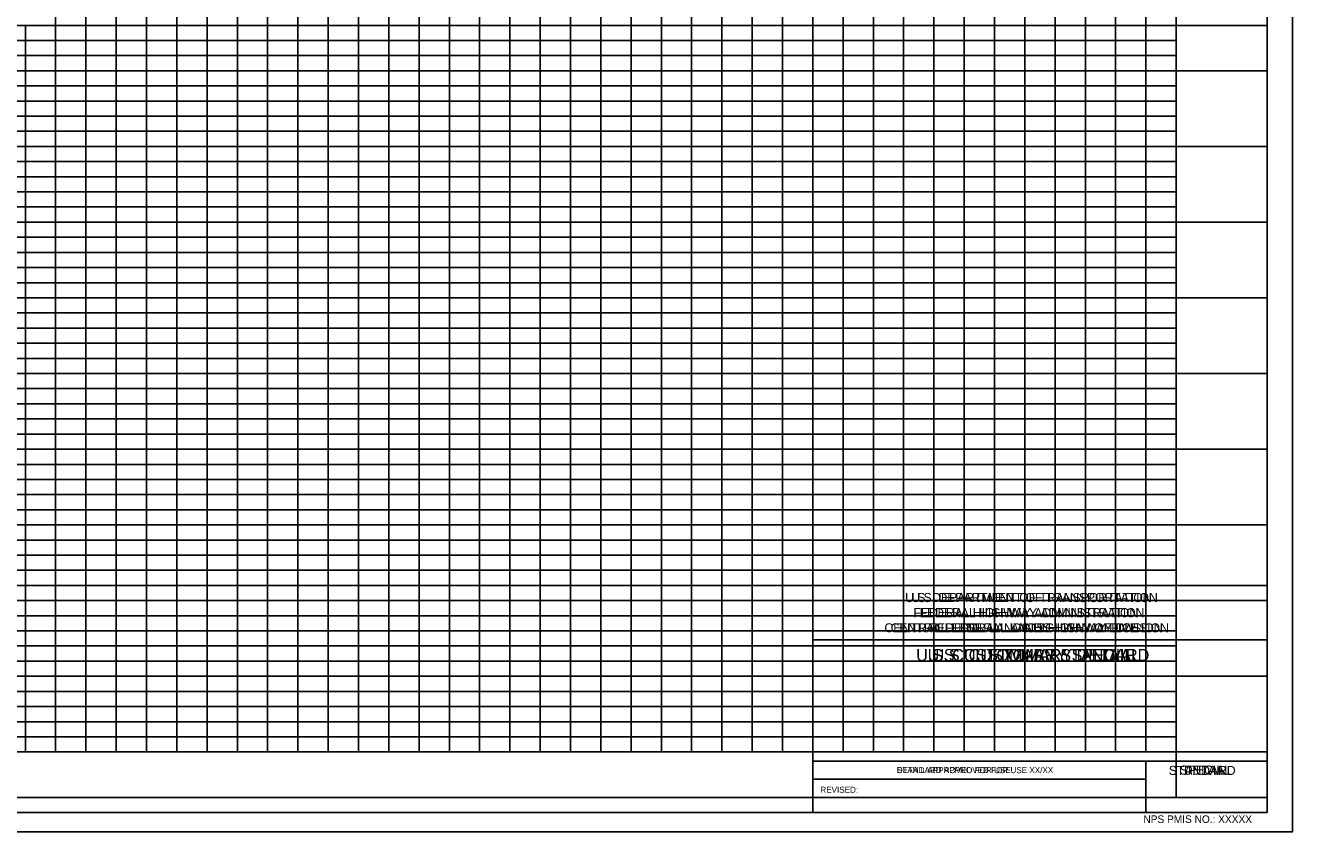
# Model space of a CAD drawing. Extents: x -87 to 2484, y -13 to 1056.
# Drawn here: x 740 to 1577, y -13 to 520 of the extents above; entities that cross this region are included whole.
import ezdxf

# ---------------------------------------------------------------- set-up
doc = ezdxf.new("R2010")
doc.units = 0
for name, color, linetype in [('D_CFL_Clip_Boundary_1', 7, 'Continuous'), ('D_CFL_Clip_Boundary_2', 7, 'Continuous'), ('D_CFL_Sheet_Border_ PlotShape', 7, 'Continuous'), ('D_CFL_Sheet_Border_Base', 7, 'Continuous'), ('D_CFL_Sheet_Border_Box', 7, 'Continuous'), ('D_CFL_Sheet_Border_Detail', 7, 'Continuous'), ('D_CFL_Sheet_Border_General', 7, 'Continuous'), ('D_CFL_Sheet_Border_NPS_Pkg', 7, 'Continuous'), ('D_CFL_Sheet_Border_Plan_Plan', 7, 'Continuous'), ('D_CFL_Sheet_Border_PnP', 7, 'Continuous'), ('D_CFL_Sheet_Border_Profile', 7, 'Continuous'), ('D_CFL_Sheet_Border_Special', 7, 'Continuous'), ('D_CFL_Sheet_Border_Standard', 7, 'Continuous')]:
    doc.layers.add(name, color=color, linetype=linetype)

msp = doc.modelspace()

# ---------------------------------------------------------------- linework, layer by layer
at = {"layer": 'D_CFL_Clip_Boundary_1'}
msp.add_lwpolyline([(0, 520), (0, 1040), (1305, 1040), (1305, 1000), (1560, 1000), (1560, 520)], close=True, dxfattribs=at)
msp.add_lwpolyline([(0, 520), (0, 1040), (1305, 1040), (1305, 1000), (1560, 1000), (1560, 520)], close=True, dxfattribs=at)
at = {"layer": 'D_CFL_Clip_Boundary_2'}
msp.add_lwpolyline([(1500, 520), (60, 520), (60, 40), (1500, 40)], close=True, dxfattribs=at)
msp.add_lwpolyline([(1500, 520), (60, 520), (60, 40), (1500, 40)], close=True, dxfattribs=at)
at = {"layer": 'D_CFL_Sheet_Border_ PlotShape'}
msp.add_lwpolyline([(-86.9, -12.66), (1576.9, -12.66), (1576.9, 1052.65), (-86.9, 1052.65)], close=True, dxfattribs=at)
msp.add_lwpolyline([(-86.9, -12.66), (1576.9, -12.66), (1576.9, 1052.65), (-86.9, 1052.65)], close=True, dxfattribs=at)
at = {"layer": 'D_CFL_Sheet_Border_Base'}
msp.add_lwpolyline([(0, 0), (1560, 0), (1560, 1040), (0, 1040)], close=True, dxfattribs=at)
msp.add_lwpolyline([(0, 0), (1560, 0), (1560, 1040), (0, 1040)], close=True, dxfattribs=at)
at = {"layer": 'D_CFL_Sheet_Border_Box'}
for p, q in [((1260, 0), (1260, 114)), ((1260, 114), (1560.01, 114)), ((1260, 0), (1260, 114)), ((1260, 114), (1560.01, 114)), ((1410.01, 57), (1410.01, 57)), ((1410.01, 57), (1410.01, 57))]:
    msp.add_line(p, q, dxfattribs=at)
at = {"layer": 'D_CFL_Sheet_Border_Detail'}
for p, q in [((1260, 114), (1560.01, 114)), ((1260, 114), (1560.01, 114)), ((1410.01, 69), (1410.01, 69)), ((1410.01, 69), (1410.01, 69)), ((1260, 34), (1560.01, 34)), ((1260, 34), (1560.01, 34)), ((1480.01, 34), (1480.01, 0)), ((1480.01, 34), (1480.01, 0)), ((1260, 22), (1480.01, 22)), ((1260, 22), (1480.01, 22))]:
    msp.add_line(p, q, dxfattribs=at)
msp.add_lwpolyline([(1560.01, 150), (1260, 150), (1260, 0)], dxfattribs=at)
msp.add_lwpolyline([(1560.01, 150), (1260, 150), (1260, 0)], dxfattribs=at)
at = {"layer": 'D_CFL_Sheet_Border_General'}
for p, q in [((1260, 114), (1560.01, 114)), ((1260, 114), (1560.01, 114)), ((1410.01, 57), (1410.01, 57)), ((1410.01, 57), (1410.01, 57))]:
    msp.add_line(p, q, dxfattribs=at)
msp.add_lwpolyline([(1560.01, 150), (1260, 150), (1260, 0)], dxfattribs=at)
msp.add_lwpolyline([(1560.01, 150), (1260, 150), (1260, 0)], dxfattribs=at)
at = {"layer": 'D_CFL_Sheet_Border_Plan_Plan'}
for p, q in [((1260, 0), (1260, 114)), ((1260, 114), (1560.01, 114)), ((1260, 0), (1260, 114)), ((1260, 114), (1560.01, 114)), ((1410.01, 57), (1410.01, 57)), ((1410.01, 57), (1410.01, 57))]:
    msp.add_line(p, q, dxfattribs=at)
at = {"layer": 'D_CFL_Sheet_Border_PnP'}
for p, q in [((0, 520), (1560, 520)), ((0, 520), (1560, 520)), ((740, 39.72), (740, 519.72)), ((740, 39.72), (740, 519.72)), ((760, 39.72), (760, 519.72)), ((760, 39.72), (760, 519.72)), ((780, 40), (780, 520)), ((780, 40), (780, 520)), ((800, 39.72), (800, 519.72)), ((800, 39.72), (800, 519.72)), ((820, 39.72), (820, 519.72)), ((820, 39.72), (820, 519.72)), ((840, 39.72), (840, 519.72)), ((840, 39.72), (840, 519.72)), ((860, 39.72), (860, 519.72)), ((860, 39.72), (860, 519.72)), ((880, 40), (880, 520)), ((880, 40), (880, 520)), ((900, 39.72), (900, 519.72)), ((900, 39.72), (900, 519.72)), ((920, 39.72), (920, 519.72)), ((920, 39.72), (920, 519.72)), ((940, 39.72), (940, 519.72)), ((940, 39.72), (940, 519.72)), ((960, 39.72), (960, 519.72)), ((960, 39.72), (960, 519.72)), ((980, 40), (980, 520)), ((980, 40), (980, 520)), ((1000, 39.72), (1000, 519.72)), ((1000, 39.72), (1000, 519.72)), ((1020, 39.72), (1020, 519.72)), ((1020, 39.72), (1020, 519.72)), ((1040, 39.72), (1040, 519.72)), ((1040, 39.72), (1040, 519.72)), ((1060, 39.72), (1060, 519.72)), ((1060, 39.72), (1060, 519.72)), ((1080, 40), (1080, 520)), ((1080, 40), (1080, 520)), ((1100, 39.72), (1100, 519.72)), ((1100, 39.72), (1100, 519.72)), ((1120, 39.72), (1120, 519.72)), ((1120, 39.72), (1120, 519.72)), ((1140, 39.72), (1140, 519.72)), ((1140, 39.72), (1140, 519.72)), ((1160, 39.72), (1160, 519.72)), ((1160, 39.72), (1160, 519.72)), ((1180, 40), (1180, 520)), ((1180, 40), (1180, 520)), ((1200, 39.72), (1200, 519.72)), ((1200, 39.72), (1200, 519.72)), ((1220, 39.72), (1220, 519.72)), ((1220, 39.72), (1220, 519.72)), ((1240, 39.72), (1240, 519.72)), ((1240, 39.72), (1240, 519.72)), ((1260, 39.72), (1260, 519.72)), ((1260, 39.72), (1260, 519.72)), ((1280, 40), (1280, 520)), ((1280, 40), (1280, 520)), ((1300, 39.72), (1300, 519.72)), ((1300, 39.72), (1300, 519.72)), ((1320, 39.72), (1320, 519.72)), ((1320, 39.72), (1320, 519.72)), ((1340, 39.72), (1340, 519.72)), ((1340, 39.72), (1340, 519.72)), ((1360, 39.72), (1360, 519.72)), ((1360, 39.72), (1360, 519.72)), ((1380, 40), (1380, 520)), ((1380, 40), (1380, 520)), ((1400, 39.72), (1400, 519.72)), ((1400, 39.72), (1400, 519.72)), ((1420, 39.72), (1420, 519.72)), ((1420, 39.72), (1420, 519.72)), ((1440, 39.72), (1440, 519.72)), ((1440, 39.72), (1440, 519.72)), ((1460, 39.72), (1460, 519.72)), ((1460, 39.72), (1460, 519.72)), ((1480, 40), (1480, 520)), ((1480, 40), (1480, 520)), ((1500, 520), (1500, 10)), ((1500, 520), (1500, 10)), ((60, 510), (1500, 510)), ((60, 510), (1500, 510)), ((60, 500), (1500, 500)), ((60, 500), (1500, 500)), ((60, 490), (1500, 490)), ((60, 490), (1500, 490)), ((1560, 490), (1500, 490)), ((1560, 490), (1500, 490)), ((60, 480), (1500, 480)), ((60, 480), (1500, 480)), ((60, 470), (1500, 470)), ((60, 470), (1500, 470)), ((60, 460), (1500, 460)), ((60, 460), (1500, 460)), ((60, 450), (1500, 450)), ((60, 450), (1500, 450)), ((60, 440), (1500, 440)), ((60, 440), (1500, 440)), ((1560, 440), (1500, 440)), ((1560, 440), (1500, 440)), ((60, 430), (1500, 430)), ((60, 430), (1500, 430)), ((60, 420), (1500, 420)), ((60, 420), (1500, 420)), ((60, 410), (1500, 410)), ((60, 410), (1500, 410)), ((60, 400), (1500, 400)), ((60, 400), (1500, 400)), ((60, 390), (1500, 390)), ((60, 390), (1500, 390)), ((1560, 390), (1500, 390)), ((1560, 390), (1500, 390)), ((60, 380), (1500, 380)), ((60, 380), (1500, 380)), ((60, 370), (1500, 370)), ((60, 370), (1500, 370)), ((60, 360), (1500, 360)), ((60, 360), (1500, 360)), ((60, 350), (1500, 350)), ((60, 350), (1500, 350)), ((60, 340), (1500, 340)), ((60, 340), (1500, 340)), ((1560, 340), (1500, 340)), ((1560, 340), (1500, 340)), ((60, 330), (1500, 330)), ((60, 330), (1500, 330)), ((60, 320), (1500, 320)), ((60, 320), (1500, 320)), ((60, 310), (1500, 310)), ((60, 310), (1500, 310)), ((60, 300), (1500, 300)), ((60, 300), (1500, 300)), ((60, 290), (1500, 290)), ((60, 290), (1500, 290)), ((1560, 290), (1500, 290)), ((1560, 290), (1500, 290)), ((60, 280), (1500, 280)), ((60, 280), (1500, 280)), ((60, 270), (1500, 270)), ((60, 270), (1500, 270)), ((60, 260), (1500, 260)), ((60, 260), (1500, 260)), ((60, 250), (1500, 250)), ((60, 250), (1500, 250)), ((60, 240), (1500, 240)), ((60, 240), (1500, 240)), ((1560, 240), (1500, 240)), ((1560, 240), (1500, 240)), ((60, 230), (1500, 230)), ((60, 230), (1500, 230)), ((60, 220), (1500, 220)), ((60, 220), (1500, 220)), ((60, 210), (1500, 210)), ((60, 210), (1500, 210)), ((60, 200), (1500, 200)), ((60, 200), (1500, 200)), ((60, 190), (1500, 190)), ((60, 190), (1500, 190)), ((1560, 190), (1500, 190)), ((1560, 190), (1500, 190)), ((60, 180), (1500, 180)), ((60, 180), (1500, 180)), ((60, 170), (1500, 170)), ((60, 170), (1500, 170)), ((60, 160), (1500, 160)), ((60, 160), (1500, 160)), ((60, 150), (1500, 150)), ((60, 150), (1500, 150)), ((60, 140), (1500, 140)), ((60, 140), (1500, 140)), ((1560, 140), (1500, 140)), ((1560, 140), (1500, 140)), ((60, 130), (1500, 130)), ((60, 130), (1500, 130)), ((60, 120), (1500, 120)), ((60, 120), (1500, 120)), ((60, 110), (1500, 110)), ((60, 110), (1500, 110)), ((60, 100), (1500, 100)), ((60, 100), (1500, 100)), ((60, 90), (1500, 90)), ((60, 90), (1500, 90)), ((1560, 90), (1500, 90)), ((1560, 90), (1500, 90)), ((60, 80), (1500, 80)), ((60, 80), (1500, 80)), ((60, 70), (1500, 70)), ((60, 70), (1500, 70)), ((60, 60), (1500, 60)), ((60, 60), (1500, 60)), ((60, 50), (1500, 50)), ((60, 50), (1500, 50)), ((60, 40), (1500, 40)), ((60, 40), (1500, 40)), ((1560, 40), (1500, 40)), ((1560, 40), (1500, 40)), ((0, 10), (1560, 10)), ((0, 10), (1560, 10))]:
    msp.add_line(p, q, dxfattribs=at)
at = {"layer": 'D_CFL_Sheet_Border_Profile'}
for p, q in [((760, 40), (760, 990)), ((760, 40), (760, 990)), ((780, 40), (780, 990)), ((780, 40), (780, 990)), ((800, 40), (800, 990)), ((800, 40), (800, 990)), ((820, 40), (820, 990)), ((820, 40), (820, 990)), ((840, 40), (840, 990)), ((840, 40), (840, 990)), ((860, 40), (860, 990)), ((860, 40), (860, 990)), ((880, 40), (880, 990)), ((880, 40), (880, 990)), ((900, 40), (900, 990)), ((900, 40), (900, 990)), ((920, 40), (920, 990)), ((920, 40), (920, 990)), ((940, 40), (940, 990)), ((940, 40), (940, 990)), ((960, 40), (960, 990)), ((960, 40), (960, 990)), ((980, 40), (980, 990)), ((980, 40), (980, 990)), ((1000, 40), (1000, 990)), ((1000, 40), (1000, 990)), ((1020, 40), (1020, 990)), ((1020, 40), (1020, 990)), ((1040, 40), (1040, 990)), ((1040, 40), (1040, 990)), ((1060, 40), (1060, 990)), ((1060, 40), (1060, 990)), ((1080, 40), (1080, 990)), ((1080, 40), (1080, 990)), ((1100, 40), (1100, 990)), ((1100, 40), (1100, 990)), ((1120, 40), (1120, 990)), ((1120, 40), (1120, 990)), ((1140, 40), (1140, 990)), ((1140, 40), (1140, 990)), ((1160, 40), (1160, 990)), ((1160, 40), (1160, 990)), ((1180, 40), (1180, 990)), ((1180, 40), (1180, 990)), ((1200, 40), (1200, 990)), ((1200, 40), (1200, 990)), ((1220, 40), (1220, 990)), ((1220, 40), (1220, 990)), ((1240, 40), (1240, 990)), ((1240, 40), (1240, 990)), ((1260, 40), (1260, 990)), ((1260, 40), (1260, 990)), ((1280, 40), (1280, 990)), ((1280, 40), (1280, 990)), ((1300, 40), (1300, 990)), ((1300, 40), (1300, 990)), ((1320, 40), (1320, 990)), ((1320, 40), (1320, 990)), ((1340, 40), (1340, 990)), ((1340, 40), (1340, 990)), ((1360, 40), (1360, 990)), ((1360, 40), (1360, 990)), ((1380, 40), (1380, 990)), ((1380, 40), (1380, 990)), ((1400, 40), (1400, 990)), ((1400, 40), (1400, 990)), ((1420, 40), (1420, 990)), ((1420, 40), (1420, 990)), ((1440, 40), (1440, 990)), ((1440, 40), (1440, 990)), ((1460, 40), (1460, 990)), ((1460, 40), (1460, 990)), ((1480, 40), (1480, 990)), ((1480, 40), (1480, 990)), ((1500, 990), (1500, 10)), ((1500, 990), (1500, 10)), ((60, 520), (1500, 520)), ((60, 520), (1500, 520)), ((60, 510), (1500, 510)), ((60, 510), (1500, 510)), ((60, 500), (1500, 500)), ((60, 500), (1500, 500)), ((60, 490), (1500, 490)), ((60, 490), (1500, 490)), ((1560, 490), (1500, 490)), ((1560, 490), (1500, 490)), ((60, 480), (1500, 480)), ((60, 480), (1500, 480)), ((60, 470), (1500, 470)), ((60, 470), (1500, 470)), ((60, 460), (1500, 460)), ((60, 460), (1500, 460)), ((60, 450), (1500, 450)), ((60, 450), (1500, 450)), ((60, 440), (1500, 440)), ((60, 440), (1500, 440)), ((1560, 440), (1500, 440)), ((1560, 440), (1500, 440)), ((60, 430), (1500, 430)), ((60, 430), (1500, 430)), ((60, 420), (1500, 420)), ((60, 420), (1500, 420)), ((60, 410), (1500, 410)), ((60, 410), (1500, 410)), ((60, 400), (1500, 400)), ((60, 400), (1500, 400)), ((60, 390), (1500, 390)), ((60, 390), (1500, 390)), ((1560, 390), (1500, 390)), ((1560, 390), (1500, 390)), ((60, 380), (1500, 380)), ((60, 380), (1500, 380)), ((60, 370), (1500, 370)), ((60, 370), (1500, 370)), ((60, 360), (1500, 360)), ((60, 360), (1500, 360)), ((60, 350), (1500, 350)), ((60, 350), (1500, 350)), ((60, 340), (1500, 340)), ((60, 340), (1500, 340)), ((1560, 340), (1500, 340)), ((1560, 340), (1500, 340)), ((60, 330), (1500, 330)), ((60, 330), (1500, 330)), ((60, 320), (1500, 320)), ((60, 320), (1500, 320)), ((60, 310), (1500, 310)), ((60, 310), (1500, 310)), ((60, 300), (1500, 300)), ((60, 300), (1500, 300)), ((60, 290), (1500, 290)), ((60, 290), (1500, 290)), ((1560, 290), (1500, 290)), ((1560, 290), (1500, 290)), ((60, 280), (1500, 280)), ((60, 280), (1500, 280)), ((60, 270), (1500, 270)), ((60, 270), (1500, 270)), ((60, 260), (1500, 260)), ((60, 260), (1500, 260)), ((60, 250), (1500, 250)), ((60, 250), (1500, 250)), ((60, 240), (1500, 240)), ((60, 240), (1500, 240)), ((1560, 240), (1500, 240)), ((1560, 240), (1500, 240)), ((60, 230), (1500, 230)), ((60, 230), (1500, 230)), ((60, 220), (1500, 220)), ((60, 220), (1500, 220)), ((60, 210), (1500, 210)), ((60, 210), (1500, 210)), ((60, 200), (1500, 200)), ((60, 200), (1500, 200)), ((60, 190), (1500, 190)), ((60, 190), (1500, 190)), ((1560, 190), (1500, 190)), ((1560, 190), (1500, 190)), ((60, 180), (1500, 180)), ((60, 180), (1500, 180)), ((60, 170), (1500, 170)), ((60, 170), (1500, 170)), ((60, 160), (1500, 160)), ((60, 160), (1500, 160)), ((60, 150), (1500, 150)), ((60, 150), (1500, 150)), ((60, 140), (1500, 140)), ((60, 140), (1500, 140)), ((1560, 140), (1500, 140)), ((1560, 140), (1500, 140)), ((60, 130), (1500, 130)), ((60, 130), (1500, 130)), ((60, 120), (1500, 120)), ((60, 120), (1500, 120)), ((60, 110), (1500, 110)), ((60, 110), (1500, 110)), ((60, 100), (1500, 100)), ((60, 100), (1500, 100)), ((60, 90), (1500, 90)), ((60, 90), (1500, 90)), ((1560, 90), (1500, 90)), ((1560, 90), (1500, 90)), ((60, 80), (1500, 80)), ((60, 80), (1500, 80)), ((60, 70), (1500, 70)), ((60, 70), (1500, 70)), ((60, 60), (1500, 60)), ((60, 60), (1500, 60)), ((60, 50), (1500, 50)), ((60, 50), (1500, 50)), ((60, 40), (1500, 40)), ((60, 40), (1500, 40)), ((1560, 40), (1500, 40)), ((1560, 40), (1500, 40)), ((0, 10), (1560, 10)), ((0, 10), (1560, 10))]:
    msp.add_line(p, q, dxfattribs=at)
at = {"layer": 'D_CFL_Sheet_Border_Special'}
for p, q in [((1260, 114), (1560.01, 114)), ((1260, 114), (1560.01, 114)), ((1410.01, 69), (1410.01, 69)), ((1410.01, 69), (1410.01, 69)), ((1260, 34), (1560.01, 34)), ((1260, 34), (1560.01, 34)), ((1480.01, 34), (1480.01, 0)), ((1480.01, 34), (1480.01, 0)), ((1260, 22), (1480.01, 22)), ((1260, 22), (1480.01, 22))]:
    msp.add_line(p, q, dxfattribs=at)
msp.add_lwpolyline([(1560.01, 150), (1260, 150), (1260, 0)], dxfattribs=at)
msp.add_lwpolyline([(1560.01, 150), (1260, 150), (1260, 0)], dxfattribs=at)
at = {"layer": 'D_CFL_Sheet_Border_Standard'}
for p, q in [((1260, 114), (1560.01, 114)), ((1260, 114), (1560.01, 114)), ((1410.01, 69), (1410.01, 69)), ((1410.01, 69), (1410.01, 69)), ((1260, 34), (1560.01, 34)), ((1260, 34), (1560.01, 34)), ((1480.01, 34), (1480.01, 0)), ((1480.01, 34), (1480.01, 0)), ((1260, 22), (1480.01, 22)), ((1260, 22), (1480.01, 22))]:
    msp.add_line(p, q, dxfattribs=at)
msp.add_lwpolyline([(1560.01, 150), (1260, 150), (1260, 0)], dxfattribs=at)
msp.add_lwpolyline([(1560.01, 150), (1260, 150), (1260, 0)], dxfattribs=at)

# ---------------------------------------------------------------- texts
at = {"layer": 'D_CFL_Sheet_Border_Detail'}
for s, height, p in [('U.S. DEPARTMENT OF TRANSPORTATION', 6, (1321.03, 139)), ('U.S. DEPARTMENT OF TRANSPORTATION', 6, (1321.03, 139)), ('FEDERAL HIGHWAY ADMINISTRATION', 6, (1326.45, 129)), ('FEDERAL HIGHWAY ADMINISTRATION', 6, (1326.45, 129)), ('CENTRAL FEDERAL LANDS HIGHWAY DIVISION', 6, (1307.33, 119)), ('CENTRAL FEDERAL LANDS HIGHWAY DIVISION', 6, (1307.33, 119)), ('U.S. CUSTOMARY DETAIL', 8, (1339.14, 100)), ('U.S. CUSTOMARY DETAIL', 8, (1339.14, 100)), ('DETAIL APPROVED FOR USE', 4, (1315.5, 26)), ('DETAIL APPROVED FOR USE', 4, (1315.5, 26)), ('DETAIL', 6, (1505.07, 25)), ('DETAIL', 6, (1505.07, 25)), ('REVISED:                                                 ', 4, (1265, 13)), ('REVISED:                                                 ', 4, (1265, 13))]:
    msp.add_text(s, height=height, dxfattribs=at).set_placement(p)
at = {"layer": 'D_CFL_Sheet_Border_General'}
for s, p in [('U.S. DEPARTMENT OF TRANSPORTATION', (1325.16, 139)), ('U.S. DEPARTMENT OF TRANSPORTATION', (1325.16, 139)), ('FEDERAL HIGHWAY ADMINISTRATION', (1330.57, 129)), ('FEDERAL HIGHWAY ADMINISTRATION', (1330.57, 129)), ('CENTRAL FEDERAL LANDS HIGHWAY DIVISION', (1311.46, 119)), ('CENTRAL FEDERAL LANDS HIGHWAY DIVISION', (1311.46, 119))]:
    msp.add_text(s, height=6, dxfattribs=at).set_placement(p)
at = {"layer": 'D_CFL_Sheet_Border_NPS_Pkg'}
msp.add_text('NPS PMIS NO.: XXXXX ', height=5, dxfattribs=at).set_placement((1478.34, -6.9))
msp.add_text('NPS PMIS NO.: XXXXX ', height=5, dxfattribs=at).set_placement((1478.34, -6.9))
at = {"layer": 'D_CFL_Sheet_Border_Special'}
for s, height, p in [('U.S. DEPARTMENT OF TRANSPORTATION', 6, (1325.16, 139)), ('U.S. DEPARTMENT OF TRANSPORTATION', 6, (1325.16, 139)), ('FEDERAL HIGHWAY ADMINISTRATION', 6, (1330.57, 129)), ('FEDERAL HIGHWAY ADMINISTRATION', 6, (1330.57, 129)), ('CENTRAL FEDERAL LANDS HIGHWAY DIVISION', 6, (1311.46, 119)), ('CENTRAL FEDERAL LANDS HIGHWAY DIVISION', 6, (1311.46, 119)), ('U.S. CUSTOMARY SPECIAL', 8, (1335.85, 100)), ('U.S. CUSTOMARY SPECIAL', 8, (1335.85, 100)), ('SPECIAL', 6, (1502.35, 25)), ('SPECIAL', 6, (1502.35, 25))]:
    msp.add_text(s, height=height, dxfattribs=at).set_placement(p)
at = {"layer": 'D_CFL_Sheet_Border_Standard'}
for s, height, p in [('U.S. DEPARTMENT OF TRANSPORTATION', 6, (1325.16, 139)), ('U.S. DEPARTMENT OF TRANSPORTATION', 6, (1325.16, 139)), ('FEDERAL HIGHWAY ADMINISTRATION', 6, (1330.57, 129)), ('FEDERAL HIGHWAY ADMINISTRATION', 6, (1330.57, 129)), ('FEDERAL LANDS HIGHWAY OFFICE', 6, (1337.17, 119)), ('FEDERAL LANDS HIGHWAY OFFICE', 6, (1337.17, 119)), ('U.S. CUSTOMARY STANDARD', 8, (1328.3, 100)), ('U.S. CUSTOMARY STANDARD', 8, (1328.3, 100)), ('STANDARD APPROVED FOR USE XX/XX', 4, (1315.67, 26)), ('STANDARD APPROVED FOR USE XX/XX', 4, (1315.67, 26)), ('STANDARD', 6, (1495.09, 24.79)), ('STANDARD', 6, (1495.09, 24.79)), ('REVISED:                                                 ', 4, (1265, 13)), ('REVISED:                                                 ', 4, (1265, 13))]:
    msp.add_text(s, height=height, dxfattribs=at).set_placement(p)

doc.saveas('drawing.dxf')
